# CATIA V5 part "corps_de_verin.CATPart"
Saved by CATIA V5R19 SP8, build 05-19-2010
Part number: corps_de_verin
Bounding box of the stored display mesh (mm): x -60 to 303, y -25 to 25, z -24.818 to 24.818
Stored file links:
  U:\Thinkmotion\Assemblage final\corps_de_verin.CATPart
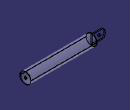
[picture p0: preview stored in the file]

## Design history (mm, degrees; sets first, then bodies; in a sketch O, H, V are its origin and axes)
Body1 (main body)
  Sketch1 on yz-plane, origin (0, 0, 0), H (0, 1, 0), V (0, 0, 1)
    circle A1 centre (0, 0) radius 25
  Pad1: profile Sketch1, direction (1, 0, 0), length 300
  Shell1: IntOffset 1.25, Face end face of Pad1, ExtOffset 0
  Sketch2 on start face of Pad1, origin (0, 0, 0), H (0, -1, 0), V (0, 0, 1)
    point P1 (-3, 40)
    line L1 (3, 19.7737) -> (3, -19.768)
    line L2 (-2.6178, -19.8223) -> (-2.6178, 19.8279)
    point P2 (3, 40)
    point P3 (3, -50)
    arc A1 centre (0, 0) radius 19.9944 from (-2.6178, -19.8223) to (3, -19.768) ccw
    arc A2 centre (0, 0) radius 20 from (3, 19.7737) to (-2.6178, 19.8279) ccw
    reference projected circle E1 centre (0, 0) radius 25 from edge [start face of Pad1 | face of Pad1 from Sketch1.A1]
    distance V L1 = 3
    distance P2 P3 = 90
    distance P1 P2 = 6
    radius A2 = 20
    vertical: L1 V, L2 V
    concentricity: A2 E1
  Pad2: profile Sketch2, direction (-1, 0, 0), length 60
  Sketch3 on face of Pad2 from Sketch2.L1, origin (0, -3, 0), H (1, 0, 0), V (0, 0, 1)
    arc A1 centre (-35, 0) radius 25 from (-35, 25) to (-35, -25) ccw
    point P1 (-35, 0)
    reference projected line E1 (-60, -24.8193) -> (-60, 24.8193) from edge [face of Pad2 from Sketch2.L1 | end face of Pad2]
    reference projected line E2 (0, 19.7737) -> (-30, 19.7737) from edge [face of Pad2 | face of Pad2 from Sketch2.L1]
    reference projected line E3 (0, -19.768) -> (-30, -19.768) from edge [face of Pad2 from Sketch2.L1 | face of Pad2]
    line L1 (-35, 25) -> (-35, 30)
    line L2 (-35, 30) -> (-70, 30)
    line L3 (-70, 30) -> (-70, -30)
    line L4 (-70, -30) -> (-30, -30)
    line L5 (-30, -30) -> (-35, -25)
    distance E2 E3 = 39.5418 (reference)
    radius A1 = 25
    coincidence: P1 H
    tangency: A1 E1
    vertical: L1 V, L3 V
    horizontal: L2 H, L4 H
  Pocket1: profile Sketch3, direction (0, 1, 0), length 30
  Sketch4 on face of Pad2 from Sketch2.L1, origin (-30.898, -3, 0.9615), H (1, 0, 0), V (0, 0, 1)
    point P1 (-4.102, -0.9615)
    reference projected arc E1 centre (-4.102, -0.9615) radius 25 from (-7.102, 23.8579) to (-7.102, -25.7808) ccw from edge [face of Pocket1 | face of Pad2 from Sketch2.L1]
    concentricity: P1 E1
  Hole1: placed by Sketch4, at (-35, -3, 0) direction (0, 1, 0), diameter 10, depth 10
  Sketch5 on end face of Pad1, origin (300, 0, 0), H (0, 1, 0), V (0, 0, 1)
    circle A1 centre (0, 0) radius 25
    reference projected circle E1 centre (0, 0) radius 25 from edge [face of Pad1 from Sketch1.A1 | end face of Pad1]
    coincidence: A1 E1
  Pad3: profile Sketch5, direction (1, 0, 0), length 3
  Sketch6 on end face of Pad3, origin (303, 0, 0), H (0, 1, 0), V (0, 0, 1)
    point P1 (0, 0)
    reference projected circle E1 centre (0, 0) radius 25 from edge [face of Pad3 | end face of Pad3]
    concentricity: P1 E1
  Hole2: placed by Sketch6, at (303, 0, 0) direction (-1, 0, 0), diameter 10, depth 10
